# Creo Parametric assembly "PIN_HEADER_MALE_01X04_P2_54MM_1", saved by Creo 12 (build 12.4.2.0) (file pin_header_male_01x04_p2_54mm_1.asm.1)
Units: Custom; MM, KILOGRAM, SECS

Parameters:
  PTC_WM_ITERATION = "0"
  PTC_WM_VERSION = "-.0"
  PTC_WM_LIFECYCLE_STATE = "In Work"
  PTC_WM_LIFECYCLE = "MO_CADDocument"
  PTC_WM_CREATED_BY = "Maximilian Roepper (Z0017RMS: MO)"
  PTC_WM_CREATED_ON = "18-Sep-26 11:36:42 AM"
  PTC_WM_MODIFIED_BY = "Maximilian Roepper (Z0017RMS: MO)"
  PTC_WM_MODIFIED_ON = "18-Sep-26 11:36:46 AM"
  PDMLINKNUMBER = "PDM000071455039"
  PTC_WM_NUMBER = "PDM000071455039"

Other parameters: WEIGHT, WEIGHT_FACTOR, WEIGHT_ADD, MC_ERRORS, SUPPLIER

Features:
  1. coordinate system
  2. imported feature
  3. component "MALE_PIN_HEADER_PRT_1_PRT_1"
  4. component "MALE_PIN_HEADER_PRT_1_PRT_1"
  5. component "MALE_PIN_HEADER_PRT_1_PRT_1"
  6. component "MALE_PIN_HEADER_PRT_1_PRT_1"

Other named items: DRW_VIEW_ORG, ROUGH-GROB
